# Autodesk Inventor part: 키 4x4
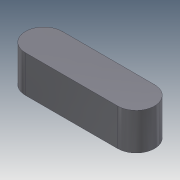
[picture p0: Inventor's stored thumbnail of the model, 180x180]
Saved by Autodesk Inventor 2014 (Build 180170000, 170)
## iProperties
Company: 한국ATC센터
Created: 2014-10
Part Number: 키 4x4
Document SubType Name: Modeling
Designer: KYOUNG IL JANG
Density: 1 g/cm^3
Mass: 0.210265 g
Surface Area: 2.35398 cm^2
Volume: 0.210265 cm^3
Material: Generic
Appearance: Steel - Polished
Author: KYOUNG IL JANG
Revision Number: 1
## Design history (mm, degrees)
sketch "스케치1"
  geometry: L1 (-5, -2)-(5, -2); L2 (5, 2)-(-5, 2); A1 r 2 centre (5, 0) between (5, -2) and (5, 2); A2 r 2 centre (-5, 0) between (-5, 2) and (-5, -2); 2 further points
  constraints: 4 end point, 4 point on circle, 4 tangent, 2 centre point, 1 horizontal, 1 horizontal alignment, 1 midpoint, 1 parallel, 1 vertical alignment
  dimensions: "d0" = 4 distance between parallel lines of L1 L2; "d1" = 14 dimension on A1 A2
extrude "돌출1" new body sketch "스케치1" stored distance "d2" = 4; taper "d3" = 0 deg
node "솔리드1"
